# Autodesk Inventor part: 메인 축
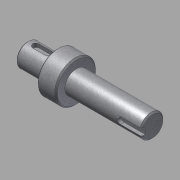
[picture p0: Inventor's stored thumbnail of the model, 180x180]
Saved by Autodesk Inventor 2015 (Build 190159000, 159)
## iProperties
Created: 2014-10
Part Number: 메인 축
Document SubType Name: Modeling
Designer: KYOUNG IL JANG
Density: 7.86 g/cm^3
Mass: 230.24 g
Surface Area: 74.3518 cm^2
Volume: 29.2926 cm^3
Material: 강철, 연강
Appearance: 금속-강(스테인리스, 브러시됨)
Author: SeoGD™ [www.esajin.kr]
Revision Number: 1
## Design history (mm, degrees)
sketch "스케치1"
  geometry: L1 (10.497, -57.5)-(102.497, -57.5); L2 (10.497, -66)-(32.497, -66); L3 (32.497, -72.5)-(46.5, -72.5); L4 (46.5, -66)-(102.497, -66); L5 (102.497, -66)-(102.497, -57.5); L6 (10.497, -66)-(10.497, -57.5); L7 (46.5, -69.749)-(46.5, -45.251) reference; L8 (46.5, -72.5)-(46.5, -66); L9 (32.497, -72.5)-(32.497, -66); L10 (32.497, -35)-(32.497, -80) reference; 2 further points
  constraints: 16 end point, 2 parallel, 2 perpendicular, 2 point on line, 1 collinear, 1 horizontal, 1 midpoint
  dimensions: "d0" = 17 diameter of L4 L1; "d1" = 30 diameter of L3 L1; "d2" = 22 distance of L2.start L2.end; "d3" = 55.99692 distance of L4.start L4.end (derived); "d5" = 17 diameter of L2 L1; "d19" = 70 distance between parallel lines of L5 L9
revolve "회전1" sketch "스케치1" stored, may be unused: angle "d4" = 90 deg
chamfer "모따기1" distance "d6" = 1; stored, may be unused: second distance "d7" = 2, angle "d8" = 45 deg
node "작업 평면1"
sketch "스케치2"
  geometry: L1 (-11, -7.5)-(-11, 7.5) reference; L2 (-4.5, 2.5)-(4.5, 2.5); L3 (4.5, -2.5)-(-4.5, -2.5); A1 r 2.5 centre (4.5, 0) between (4.5, -2.5) and (4.5, 2.5); A2 r 2.5 centre (-4.5, 0) between (-4.5, 2.5) and (-4.5, -2.5); 2 further points
  constraints: 4 end point, 4 point on circle, 4 tangent, 2 centre point, 1 horizontal alignment, 1 midpoint, 1 parallel, 1 perpendicular
  dimensions: "d9" = 5 distance between parallel lines of L3 L2; "d10" = 14 dimension on A1 A2; "d11" = 4 distance edge to line of A2 L1
extrude "돌출1" cut sketch "스케치2" distance "d12" = 3; taper "d13" = 0 deg
node "작업 평면2"
sketch "스케치3"
  geometry: L1 (27.998, 7.5)-(27.998, -7.5) reference; L2 (27.998, 2.5)-(12.498, 2.5); L3 (12.498, -2.5)-(27.998, -2.5); A1 r 2.5 centre (12.498, 0) between (12.498, 2.5) and (12.498, -2.5); 2 further points
  constraints: 4 end point, 2 perpendicular, 2 point on circle, 2 point on line, 2 tangent, 1 centre point, 1 horizontal alignment, 1 midpoint
  dimensions: "d14" = 5 distance between parallel lines of L3 L2; "d15" = 18 dimension on A1 L1
extrude "돌출2" cut sketch "스케치3" distance "d16" = 3; taper "d17" = 0 deg
node "솔리드1"
node "참조4"
node "참조5"
